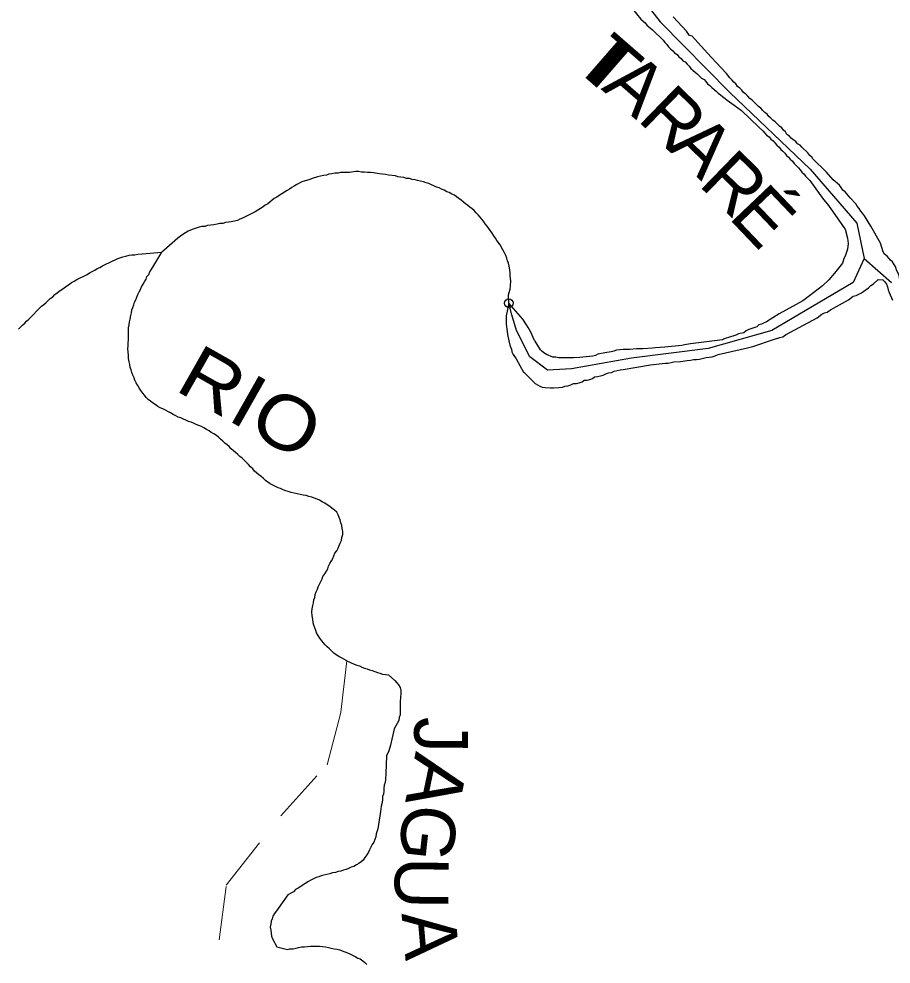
# Model space of a CAD drawing. Extents: x 652.3 to 678, y 7316.9 to 7344.9.
# Drawn here: x 655.74 to 657.36, y 7337.708 to 7339.464 of the extents above; entities that cross this region are included whole.
import ezdxf
from ezdxf.enums import TextEntityAlignment as Align

# ---------------------------------------------------------------- set-up
doc = ezdxf.new("R2010")
doc.units = 0
doc.header["$LTSCALE"] = 0.032
doc.header["$PDMODE"] = 32
doc.header["$PDSIZE"] = 0.016
doc.linetypes.add('SHORT_DASHED', pattern=[2.7, 1.5, -1.2])
for name, color, linetype, lineweight in [('2', 7, 'Continuous', 25), ('21', 7, 'SHORT_DASHED', 13), ('55', 7, 'Continuous', 25), ('7', 7, 'Continuous', 25)]:
    doc.layers.add(name, color=color, linetype=linetype, lineweight=lineweight)
doc.layers.add('61', color=7, linetype='Continuous')

msp = doc.modelspace()

# ---------------------------------------------------------------- linework, layer by layer
at = {"layer": '2'}
for points in [[(656.8793, 7339.4835), (656.8952, 7339.4636), (656.9032, 7339.4565), (656.9063, 7339.4525), (656.9103, 7339.4493), (656.9167, 7339.4437), (656.9366, 7339.4246), (656.9398, 7339.4199), (656.9437, 7339.4167), (656.9469, 7339.4119), (656.9509, 7339.4079), (656.9549, 7339.4047), (656.9581, 7339.4008), (656.9628, 7339.3976), (656.966, 7339.3936), (656.97, 7339.3904), (656.9732, 7339.3864), (656.978, 7339.3841), (656.9811, 7339.3801), (656.9851, 7339.3761), (656.9883, 7339.3721), (656.9923, 7339.3681), (656.9963, 7339.365), (657.0002, 7339.3618), (657.0042, 7339.3578), (657.0082, 7339.3538), (657.013, 7339.3514), (657.0162, 7339.3475), (657.0193, 7339.3435), (657.0233, 7339.3403), (657.0273, 7339.3363), (657.0313, 7339.3331), (657.0353, 7339.33), (657.0392, 7339.326), (657.0432, 7339.3228), (657.0472, 7339.3196), (657.052, 7339.3164), (657.0559, 7339.3132), (657.0599, 7339.3101), (657.0647, 7339.3069), (657.0687, 7339.3037), (657.0822, 7339.2941), (657.1148, 7339.2631), (657.122, 7339.256)], [(657.2135, 7339.2066), (657.2095, 7339.2106), (657.2055, 7339.2154), (657.1944, 7339.2257), (657.1912, 7339.2297), (657.1864, 7339.2321), (657.1832, 7339.2361), (657.1785, 7339.2392), (657.1745, 7339.2424), (657.1713, 7339.2464), (657.1665, 7339.2496), (657.1642, 7339.2544), (657.1602, 7339.2575), (657.157, 7339.2615), (657.153, 7339.2647), (657.149, 7339.2687), (657.1451, 7339.2727), (657.1403, 7339.2758), (657.1371, 7339.2798), (657.1331, 7339.283), (657.1299, 7339.287), (657.126, 7339.2902), (657.122, 7339.2941), (657.118, 7339.2981), (657.114, 7339.3013), (657.11, 7339.3053), (657.1061, 7339.3093), (657.1021, 7339.3132), (657.0981, 7339.3164), (657.0941, 7339.3204), (657.0902, 7339.3244), (657.0862, 7339.3276), (657.083, 7339.3315), (657.079, 7339.3355), (657.075, 7339.3387), (657.0719, 7339.3435), (657.0679, 7339.3467), (657.0647, 7339.3506), (657.0607, 7339.3546), (657.0543, 7339.3626), (657.0257, 7339.3928), (657.0257, 7339.3928), (657.001, 7339.4199), (656.9907, 7339.4318), (656.9859, 7339.4334), (656.9803, 7339.4413), (656.9557, 7339.4676)], [(657.122, 7339.256), (657.126, 7339.252), (657.1291, 7339.248), (657.1339, 7339.2448), (657.1371, 7339.2408), (657.1411, 7339.2377), (657.1443, 7339.2337), (657.1482, 7339.2297), (657.1522, 7339.2257), (657.1554, 7339.2217), (657.1594, 7339.2186), (657.1626, 7339.2146), (657.1657, 7339.2106), (657.1697, 7339.2074), (657.1729, 7339.2034), (657.1769, 7339.1995), (657.1801, 7339.1955), (657.184, 7339.1915), (657.188, 7339.1875), (657.1912, 7339.1835), (657.1944, 7339.1796), (657.1984, 7339.1764), (657.2015, 7339.1716), (657.2095, 7339.1637), (657.235, 7339.1286), (657.2421, 7339.1199), (657.2485, 7339.1111), (657.2732, 7339.0761), (657.2748, 7339.0737), (657.2795, 7339.057), (657.2803, 7339.0467), (657.2795, 7339.0363), (657.2748, 7339.0236), (657.2724, 7339.0188), (657.27, 7339.0101)], [(657.2525, 7339.1652), (657.2405, 7339.1796), (657.2143, 7339.205), (657.2135, 7339.2066)], [(657.3225, 7339.0793), (657.3106, 7339.0984), (657.3074, 7339.1032), (657.3042, 7339.1072), (657.301, 7339.1119), (657.297, 7339.1159), (657.2946, 7339.1207), (657.2843, 7339.1318), (657.2748, 7339.143), (657.2708, 7339.1461), (657.2676, 7339.1509), (657.2644, 7339.1549), (657.2525, 7339.1652)], [(657.3408, 7339.0475), (657.3225, 7339.0793), (657.3225, 7339.0793)], [(657.3798, 7338.9687), (657.379, 7338.9727), (657.3758, 7338.9822), (657.375, 7338.9878), (657.3702, 7338.9974), (657.3694, 7339.0029), (657.3631, 7339.0125), (657.3591, 7339.0157), (657.3527, 7339.0236), (657.348, 7339.0268), (657.3456, 7339.0316), (657.3408, 7339.0475)], [(657.27, 7339.0101), (657.2628, 7339.0013), (657.2549, 7338.9918), (657.2445, 7338.9791), (657.2326, 7338.9679)], [(656.8626, 7338.8128), (656.9135, 7338.8215), (656.935, 7338.8239), (656.9406, 7338.8247), (656.9461, 7338.8247), (656.9517, 7338.8255), (656.9565, 7338.8271), (656.9692, 7338.8279), (656.9811, 7338.8295), (656.9875, 7338.8303), (656.9931, 7338.8311), (656.9986, 7338.8311), (657.0042, 7338.8318), (657.0169, 7338.835), (657.0225, 7338.8358), (657.0281, 7338.8366), (657.0337, 7338.8382), (657.0392, 7338.8406), (657.0933, 7338.8533), (657.1037, 7338.8557), (657.1435, 7338.8692), (657.1538, 7338.8724), (657.1594, 7338.8732), (657.1642, 7338.8772), (657.223, 7338.909), (657.2318, 7338.9154), (657.2366, 7338.9178), (657.2413, 7338.9194), (657.2477, 7338.9234), (657.2811, 7338.9425), (657.2899, 7338.9488), (657.2954, 7338.9504), (657.3002, 7338.9528), (657.305, 7338.9552), (657.3098, 7338.9584), (657.3137, 7338.9615), (657.3185, 7338.9647), (657.3225, 7338.9687), (657.3273, 7338.9719), (657.336, 7338.9798), (657.3448, 7338.9791), (657.3488, 7338.9759), (657.3519, 7338.9711), (657.3535, 7338.9663), (657.3551, 7338.9608), (657.3567, 7338.956), (657.3631, 7338.9417)], [(657.2326, 7338.9679), (657.2087, 7338.9496), (657.196, 7338.9401), (657.1522, 7338.9162), (657.1291, 7338.9011), (657.1244, 7338.8995), (657.1196, 7338.8971), (657.1148, 7338.8955), (657.1108, 7338.8923), (657.0957, 7338.8868), (657.0909, 7338.8844), (657.087, 7338.8812), (657.0766, 7338.8788), (657.0719, 7338.8764), (657.0583, 7338.8724), (657.0536, 7338.8708), (657.0488, 7338.8692), (657.0472, 7338.8677), (656.9875, 7338.8605), (656.9764, 7338.8589), (656.9716, 7338.8573), (656.9398, 7338.8541), (656.9223, 7338.8533), (656.9167, 7338.8525), (656.8992, 7338.8509), (656.8873, 7338.8509), (656.8745, 7338.8502), (656.8626, 7338.8502), (656.8499, 7338.8486), (656.8451, 7338.847), (656.8403, 7338.8454), (656.8284, 7338.8438), (656.8156, 7338.8414), (656.8109, 7338.839), (656.8061, 7338.8374), (656.7814, 7338.835), (656.7703, 7338.8342), (656.7647, 7338.8342), (656.7591, 7338.8342), (656.7536, 7338.8342), (656.748, 7338.8342), (656.7424, 7338.8342), (656.7377, 7338.8358), (656.7321, 7338.8358), (656.7202, 7338.8406), (656.7154, 7338.8438), (656.7114, 7338.847), (656.709, 7338.8494), (656.6987, 7338.8653), (656.6979, 7338.8669), (656.6907, 7338.882), (656.6859, 7338.8907), (656.6828, 7338.8955), (656.6764, 7338.9066)], [(656.6501, 7338.9361), (656.6501, 7338.9361), (656.6454, 7338.9122)], [(656.6764, 7338.9066), (656.6501, 7338.9361), (656.6501, 7338.9361)], [(656.6454, 7338.9122), (656.6454, 7338.9106), (656.6454, 7338.8971), (656.647, 7338.8836), (656.6477, 7338.878), (656.6501, 7338.8661), (656.6525, 7338.8557), (656.6549, 7338.8509), (656.6557, 7338.8454), (656.6581, 7338.8406), (656.6637, 7338.8326), (656.6772, 7338.808), (656.678, 7338.808), (656.6987, 7338.7865), (656.7074, 7338.7817), (656.7122, 7338.7801), (656.7178, 7338.7793), (656.7273, 7338.7785), (656.7329, 7338.7785), (656.7432, 7338.7793), (656.7496, 7338.7801), (656.7544, 7338.7817), (656.7599, 7338.7825), (656.7655, 7338.7841), (656.7703, 7338.7865), (656.7759, 7338.7865), (656.7806, 7338.7881), (656.7862, 7338.7897), (656.7902, 7338.7929), (656.7957, 7338.7929), (656.8005, 7338.7945), (656.8053, 7338.796), (656.8093, 7338.7992), (656.8148, 7338.8), (656.8204, 7338.8008), (656.8252, 7338.8024), (656.83, 7338.8048), (656.8355, 7338.8064), (656.8411, 7338.8072), (656.8459, 7338.8096), (656.857, 7338.812), (656.8626, 7338.8128)]]:
    msp.add_lwpolyline(points, dxfattribs=at)
at = {"layer": '21'}
msp.add_lwpolyline([(656.8791, 7335.7466), (656.7364, 7335.7861), (656.6245, 7335.8249), (656.5319, 7335.9003), (656.3618, 7336.3504), (656.2606, 7336.6024), (656.2305, 7336.7191), (656.2154, 7336.8224), (656.2456, 7336.9215), (656.3338, 7337.04), (656.3877, 7337.1261), (656.4006, 7337.1929), (656.3898, 7337.2489), (656.3274, 7337.3243), (656.2369, 7337.3717), (656.2068, 7337.4277), (656.1422, 7337.5747), (656.1121, 7337.7535), (656.125, 7337.8547), (656.2262, 7337.984), (656.3123, 7338.0787), (656.3381, 7338.1765), (656.3493, 7338.2715)], dxfattribs=at)
at = {"layer": '55'}
for points in [[(656.859, 7339.5895), (656.8723, 7339.5339), (656.9315, 7339.4588), (657.0607, 7339.3274), (657.2098, 7339.1848), (657.2967, 7339.0846), (657.31, 7339.0189), (657.29, 7338.9743), (657.1386, 7338.8852), (657.0206, 7338.8518), (656.8781, 7338.834), (656.7668, 7338.814), (656.7222, 7338.8117), (656.6888, 7338.8362), (656.6644, 7338.8852), (656.6555, 7338.9142), (656.6501, 7338.9361)], [(657.31, 7339.0189), (657.3612, 7338.9743)]]:
    msp.add_lwpolyline(points, dxfattribs=at)
at = {"layer": '7'}
for points in [[(656.6501, 7338.9361), (656.6493, 7338.9512), (656.6509, 7338.956), (656.6525, 7338.9623), (656.6533, 7338.9679), (656.6541, 7338.9775), (656.6525, 7338.987), (656.6525, 7338.9926), (656.6517, 7338.9981), (656.6509, 7339.0045), (656.6493, 7339.0101), (656.6477, 7339.0149), (656.6462, 7339.0196), (656.6446, 7339.0244), (656.6422, 7339.0292), (656.639, 7339.0348), (656.6342, 7339.0443), (656.6279, 7339.0523), (656.6255, 7339.057), (656.6223, 7339.061), (656.6191, 7339.0658), (656.6159, 7339.0706), (656.6127, 7339.0745), (656.6096, 7339.0793), (656.6064, 7339.0833), (656.6032, 7339.0881), (656.5968, 7339.096), (656.5928, 7339.1), (656.5897, 7339.104), (656.5857, 7339.108), (656.5817, 7339.1111), (656.5777, 7339.1143), (656.5738, 7339.1175), (656.5698, 7339.1207), (656.5658, 7339.1239), (656.5618, 7339.1271), (656.557, 7339.1302), (656.5531, 7339.1334), (656.5491, 7339.1366), (656.5443, 7339.1382), (656.5395, 7339.1414), (656.5348, 7339.143), (656.53, 7339.1461), (656.5252, 7339.1477), (656.5204, 7339.1501), (656.5157, 7339.1517), (656.5109, 7339.1541), (656.5061, 7339.1557), (656.5013, 7339.1581), (656.4966, 7339.1597), (656.4918, 7339.1613), (656.4862, 7339.1629), (656.4807, 7339.1637), (656.4759, 7339.1652), (656.4703, 7339.166), (656.4655, 7339.1676), (656.46, 7339.1676), (656.4552, 7339.1692), (656.4496, 7339.17), (656.4441, 7339.1708), (656.4393, 7339.1724), (656.4265, 7339.174), (656.421, 7339.1748), (656.4154, 7339.1756), (656.4098, 7339.1764), (656.3987, 7339.178), (656.3931, 7339.1788), (656.3876, 7339.1788), (656.382, 7339.1796), (656.3764, 7339.1796), (656.3709, 7339.1804), (656.3653, 7339.1804), (656.3541, 7339.1788), (656.3374, 7339.1788), (656.3327, 7339.1772), (656.3271, 7339.1772), (656.3215, 7339.1764), (656.3159, 7339.1756), (656.3112, 7339.174), (656.3056, 7339.1732), (656.3, 7339.1716), (656.2945, 7339.1708), (656.2849, 7339.1676), (656.2801, 7339.166), (656.2658, 7339.1613), (656.2563, 7339.1565), (656.2515, 7339.1533), (656.2467, 7339.1509), (656.2427, 7339.1477), (656.238, 7339.1454), (656.2332, 7339.1422), (656.2284, 7339.139), (656.2236, 7339.1358), (656.2189, 7339.1326), (656.2141, 7339.1302), (656.2101, 7339.1271), (656.2061, 7339.1239), (656.2022, 7339.1207), (656.1974, 7339.1183), (656.1934, 7339.1151), (656.1886, 7339.1119)], [(656.1886, 7339.1119), (656.1839, 7339.1087), (656.1791, 7339.1056), (656.1552, 7339.0936), (656.1504, 7339.092), (656.1457, 7339.0897), (656.1401, 7339.0881), (656.1345, 7339.0873), (656.129, 7339.0865), (656.1234, 7339.0857), (656.1186, 7339.0841), (656.113, 7339.0841), (656.1083, 7339.0825), (656.1019, 7339.0817), (656.0963, 7339.0809), (656.09, 7339.0801), (656.0852, 7339.0785), (656.0796, 7339.0785), (656.0749, 7339.0769), (656.0637, 7339.0737), (656.0589, 7339.0714), (656.0542, 7339.0698), (656.0494, 7339.0666), (656.0446, 7339.0634), (656.0398, 7339.0602), (656.0351, 7339.057), (656.0091, 7339.0336), (656.0056, 7339.0308)], [(655.7391, 7338.8875), (655.7431, 7338.8915), (655.747, 7338.8955), (655.751, 7338.8987), (655.7542, 7338.9027), (655.7582, 7338.9066), (655.782, 7338.9305), (655.786, 7338.9337), (655.79, 7338.9369), (655.794, 7338.9409), (655.798, 7338.9448), (655.8027, 7338.948), (655.8067, 7338.952), (655.8107, 7338.9552), (655.8147, 7338.9584), (655.8194, 7338.9615), (655.8242, 7338.9647), (655.829, 7338.9679), (655.8338, 7338.9711), (655.8377, 7338.9743), (655.8425, 7338.9767), (655.8473, 7338.9798), (655.8664, 7338.9894), (655.8712, 7338.9926), (655.8759, 7338.995), (655.8807, 7338.9974), (655.8855, 7339.0005), (655.8903, 7339.0021), (655.895, 7339.0053), (655.9141, 7339.0149), (655.9189, 7339.0164), (655.9237, 7339.0188), (655.9332, 7339.022), (655.9388, 7339.0236), (655.9444, 7339.0252), (655.9499, 7339.026), (655.9555, 7339.026), (655.9611, 7339.0268), (655.969, 7339.0276), (656.0056, 7339.0308)], [(656.2022, 7338.6035), (656.1982, 7338.6067), (656.1942, 7338.6106), (656.1902, 7338.6138), (656.1855, 7338.617), (656.1815, 7338.621), (656.1775, 7338.6242), (656.1743, 7338.6282), (656.1703, 7338.6321), (656.1664, 7338.6361), (656.1624, 7338.6401), (656.1584, 7338.6441), (656.1544, 7338.648), (656.1504, 7338.6512), (656.1465, 7338.6552), (656.1425, 7338.6584), (656.1385, 7338.6616), (656.1345, 7338.6656), (656.1306, 7338.6695), (656.1266, 7338.6727), (656.1226, 7338.6759), (656.1186, 7338.6799), (656.1146, 7338.6831), (656.1107, 7338.687), (656.1067, 7338.6902), (656.1019, 7338.6934), (656.0971, 7338.6958), (656.0932, 7338.699), (656.0884, 7338.7014), (656.0836, 7338.7045), (656.0788, 7338.7069), (656.0741, 7338.7085), (656.0693, 7338.7109), (656.0645, 7338.7133), (656.0597, 7338.7149), (656.055, 7338.7165), (656.0502, 7338.7189), (656.0454, 7338.7205), (656.0406, 7338.7228), (656.0359, 7338.7244), (656.0311, 7338.7268), (656.0263, 7338.7292), (656.0215, 7338.7324), (656.0168, 7338.7348), (656.012, 7338.7372), (656.0072, 7338.7395), (656.0024, 7338.7419), (655.9977, 7338.7443), (655.9929, 7338.7475), (655.9881, 7338.7507), (655.9841, 7338.7539), (655.9802, 7338.7571), (655.9762, 7338.761), (655.973, 7338.765), (655.9698, 7338.769), (655.9666, 7338.7738), (655.9635, 7338.7785), (655.9611, 7338.7833), (655.9579, 7338.7881), (655.9555, 7338.7929), (655.9539, 7338.7976), (655.9515, 7338.8024), (655.9499, 7338.8072), (655.9483, 7338.812), (655.9467, 7338.8167), (655.946, 7338.8223), (655.9444, 7338.8271), (655.9436, 7338.8334), (655.9436, 7338.839), (655.9428, 7338.8454), (655.942, 7338.8509), (655.9428, 7338.8565), (655.9428, 7338.8621), (655.9436, 7338.8677), (655.9436, 7338.8732), (655.9436, 7338.8788), (655.9436, 7338.8844), (655.9436, 7338.8899), (655.9444, 7338.8955), (655.9452, 7338.9011), (655.9467, 7338.9066), (655.9475, 7338.913), (655.9491, 7338.9178), (655.9499, 7338.9234), (655.9515, 7338.9281), (655.9531, 7338.9329), (655.9547, 7338.9377), (655.9571, 7338.9425), (655.9587, 7338.9472), (655.9611, 7338.952), (655.9635, 7338.9568), (655.9658, 7338.9615), (655.9674, 7338.9663), (655.9706, 7338.9711), (655.973, 7338.9759), (655.9762, 7338.9806), (655.9778, 7338.9854), (655.981, 7338.9894), (655.9834, 7338.9942), (655.9889, 7339.0029), (656.0056, 7339.0308)], [(656.3493, 7338.2715), (656.339, 7338.2773), (656.3342, 7338.2796), (656.3295, 7338.2828), (656.3247, 7338.286), (656.3207, 7338.29), (656.3167, 7338.294), (656.3128, 7338.2979), (656.3088, 7338.3011), (656.3056, 7338.3051), (656.3024, 7338.3091), (656.2992, 7338.3139), (656.2961, 7338.3186), (656.2929, 7338.3234), (656.2913, 7338.3282), (656.2897, 7338.333), (656.2881, 7338.3377), (656.2865, 7338.3425), (656.2857, 7338.3489), (656.2849, 7338.3552), (656.2841, 7338.3624), (656.2849, 7338.368), (656.2857, 7338.3743), (656.2873, 7338.3791), (656.2881, 7338.3847), (656.2897, 7338.3894), (656.2905, 7338.395), (656.2921, 7338.3998), (656.2945, 7338.4046), (656.2961, 7338.4093), (656.2984, 7338.4141), (656.3008, 7338.4189), (656.3032, 7338.4237), (656.3048, 7338.4284), (656.308, 7338.4332), (656.3112, 7338.438), (656.3136, 7338.4428), (656.3152, 7338.4475), (656.3175, 7338.4523), (656.3207, 7338.4571), (656.3231, 7338.4619), (656.3247, 7338.4666), (656.3271, 7338.4714), (656.3303, 7338.4762), (656.3327, 7338.481), (656.335, 7338.4857), (656.3366, 7338.4905), (656.339, 7338.4953), (656.3398, 7338.5008), (656.3414, 7338.5064), (656.3414, 7338.512), (656.3406, 7338.5176), (656.3398, 7338.5231), (656.3382, 7338.5279), (656.3366, 7338.5335), (656.335, 7338.5382), (656.3327, 7338.543), (656.3303, 7338.5478), (656.3263, 7338.5518), (656.3215, 7338.555), (656.3175, 7338.5581), (656.3128, 7338.5613), (656.308, 7338.5645), (656.3032, 7338.5669), (656.2984, 7338.5701), (656.2937, 7338.5717), (656.2889, 7338.574), (656.2841, 7338.5756), (656.2786, 7338.5772), (656.2738, 7338.5788), (656.2682, 7338.5796), (656.2626, 7338.5804), (656.2571, 7338.582), (656.2515, 7338.5828), (656.2459, 7338.5844), (656.2404, 7338.586), (656.2356, 7338.5876), (656.2308, 7338.5892), (656.226, 7338.5916), (656.2213, 7338.5931), (656.2165, 7338.5955), (656.2117, 7338.5979), (656.2069, 7338.6003), (656.2022, 7338.6035)], [(656.3493, 7338.2715), (656.3493, 7338.2715), (656.3629, 7338.2653)], [(656.3629, 7338.2653), (656.3677, 7338.2637), (656.3724, 7338.2621), (656.3772, 7338.2597), (656.382, 7338.2582), (656.3868, 7338.2566), (656.3915, 7338.255), (656.3963, 7338.2534), (656.4011, 7338.2518), (656.4059, 7338.2502), (656.4106, 7338.2486), (656.4154, 7338.247), (656.421, 7338.2462), (656.4265, 7338.2454)], [(656.4265, 7338.2454), (656.4385, 7338.2351), (656.4417, 7338.2311), (656.4448, 7338.2271), (656.448, 7338.2224), (656.4496, 7338.2168), (656.4496, 7338.2112), (656.448, 7338.1961), (656.448, 7338.1714), (656.4464, 7338.1667), (656.4456, 7338.1611), (656.4369, 7338.1452), (656.4305, 7338.1149), (656.4273, 7338.1046), (656.4226, 7338.095), (656.4218, 7338.0624), (656.421, 7338.0513), (656.4202, 7338.0457), (656.4186, 7338.0409), (656.4178, 7338.0354), (656.4178, 7338.0298), (656.417, 7338.0242), (656.4154, 7338.0195), (656.4154, 7338.0139), (656.4146, 7338.0083), (656.413, 7338.0019), (656.4114, 7337.9916), (656.4067, 7337.9598), (656.4035, 7337.9502), (656.4027, 7337.9447), (656.4011, 7337.9399), (656.3995, 7337.9351), (656.3963, 7337.9303), (656.3939, 7337.9256), (656.3915, 7337.9208), (656.3892, 7337.916), (656.386, 7337.9112), (656.3828, 7337.9065), (656.3796, 7337.9017), (656.3756, 7337.8985), (656.3716, 7337.8953), (656.3669, 7337.8929), (656.3621, 7337.8898), (656.3573, 7337.8882), (656.3525, 7337.8858), (656.3478, 7337.8842), (656.343, 7337.8826), (656.3382, 7337.881), (656.3327, 7337.8802), (656.3279, 7337.8786), (656.3223, 7337.8778), (656.3175, 7337.8762), (656.312, 7337.8746), (656.3064, 7337.8738), (656.3016, 7337.8722), (656.2969, 7337.8707), (656.2921, 7337.8691), (656.2873, 7337.8667), (656.2825, 7337.8643), (656.2778, 7337.8619), (656.273, 7337.8587), (656.2682, 7337.8555), (656.2634, 7337.8524), (656.2587, 7337.8492), (656.2539, 7337.8468), (656.2499, 7337.8428), (656.2396, 7337.8372), (656.2213, 7337.8118), (656.2149, 7337.8022), (656.2117, 7337.7975), (656.2101, 7337.7927), (656.2085, 7337.7879), (656.2077, 7337.7823), (656.2069, 7337.7768), (656.2077, 7337.7712), (656.2085, 7337.7656), (656.2093, 7337.7601), (656.2109, 7337.7553), (656.2189, 7337.7402), (656.2388, 7337.7354), (656.2435, 7337.737), (656.2491, 7337.737), (656.2547, 7337.7378), (656.2595, 7337.7394), (656.265, 7337.7402), (656.2706, 7337.7402), (656.2762, 7337.741), (656.2817, 7337.7418), (656.2873, 7337.7418), (656.2929, 7337.7418), (656.2984, 7337.7418), (656.304, 7337.741), (656.3096, 7337.7402), (656.3152, 7337.7394), (656.3199, 7337.7378), (656.3255, 7337.737), (656.3311, 7337.7362), (656.3358, 7337.7346), (656.3406, 7337.733), (656.3454, 7337.7314), (656.3502, 7337.729)], [(656.3502, 7337.729), (656.3549, 7337.7274), (656.3597, 7337.725), (656.3645, 7337.7227), (656.3693, 7337.7195), (656.374, 7337.7179), (656.3788, 7337.7147), (656.3828, 7337.7115), (656.386, 7337.7075)]]:
    msp.add_lwpolyline(points, dxfattribs=at)
msp.add_point((656.6501, 7338.9361), dxfattribs=at)

# ---------------------------------------------------------------- texts
at = {"layer": '61'}
for s, rotation, p in [('T', 318.948, (656.8088, 7339.3403)), ('A', 318.948, (656.8538, 7339.3047)), ('R', 315.849, (656.9218, 7339.2432)), ('A', 315.849, (656.9763, 7339.1926)), ('R', 315.849, (657.0352, 7339.1225)), ('É', 313.63, (657.0873, 7339.063)), ('J', 269.477, (656.4743, 7338.1344)), ('G', 263.758, (656.4506, 7337.9568)), ('U', 269.351, (656.438, 7337.8594)), ('A', 274.944, (656.4545, 7337.7578))]:
    msp.add_text(s, height=0.1, rotation=rotation, dxfattribs=at).set_placement(p, align=Align.CENTER)
for s, rotation, width, p in [('I', 318.948, 1.85, (656.8012, 7339.3469)), ('RIO', 330.459, 1.15, (656.146, 7338.7083)), ('A', 258.166, 1.1, (656.4674, 7338.0568))]:
    msp.add_text(s, height=0.1, rotation=rotation, dxfattribs=dict(at, width=width)).set_placement(p, align=Align.CENTER)

doc.saveas('drawing.dxf')
